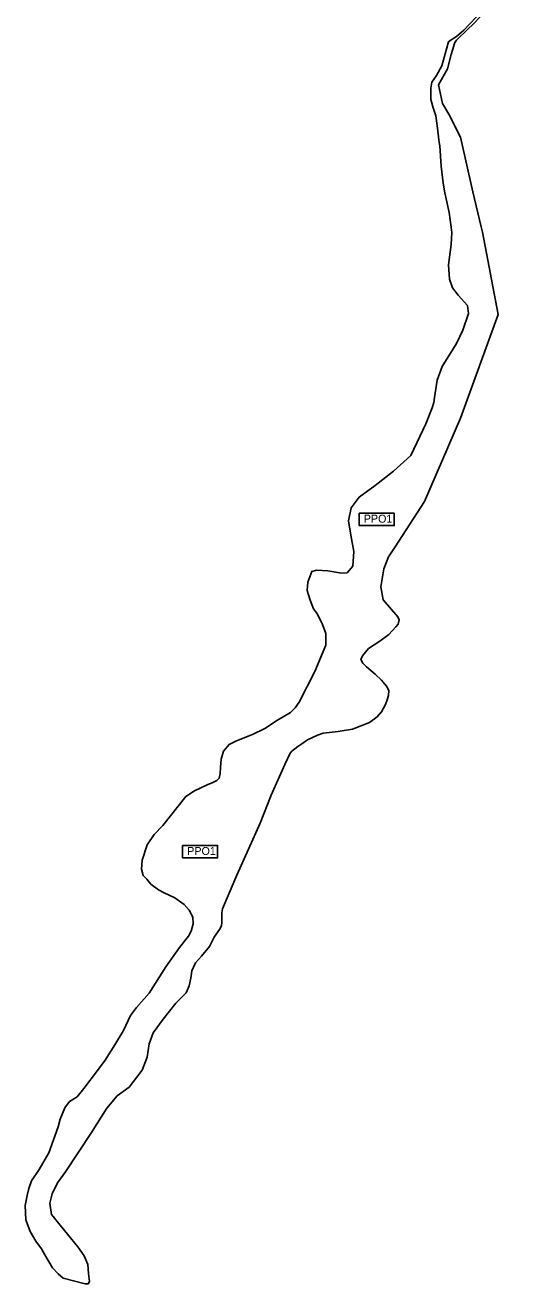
# Model space of a CAD drawing. Extents: x -545342 to -528609, y -1041871 to -1035695.
# Drawn here: x -543416 to -542812, y -1041655 to -1040083 of the extents above; entities that cross this region are included whole.
import ezdxf

# ---------------------------------------------------------------- set-up
doc = ezdxf.new("R2010")
doc.units = 0
doc.layers.add('Vrstva 61', color=7, linetype='Continuous')
doc.layers.add('Vrstva 7', color=7, linetype='Continuous')

msp = doc.modelspace()

# ---------------------------------------------------------------- linework, layer by layer
at = {"layer": 'Vrstva 61'}
for points in [[(-542862.3, -1040087.3), (-542856.8, -1040082), (-542835.7, -1040060.5), (-542826.2, -1040049.6), (-542818.1, -1040039.5), (-542817.2, -1040038.4), (-542811.6, -1040031.3), (-542814.1, -1040031.2), (-542816.3, -1040032.9), (-542827.5, -1040046.1), (-542844.5, -1040064.4), (-542867.8, -1040088.9), (-542877.2, -1040096.9), (-542883.6, -1040101.1)], [(-542877, -1040101.7), (-542862.3, -1040087.3)], [(-542883.6, -1040335.1), (-542882.7, -1040342), (-542883.5, -1040356.9), (-542887, -1040382.4), (-542885.9, -1040400), (-542881.9, -1040410.9), (-542874.9, -1040420.2), (-542863.3, -1040433.2), (-542862.2, -1040443.1), (-542869.3, -1040464.1), (-542877.2, -1040480.4), (-542894.9, -1040509.3), (-542901.3, -1040526.4), (-542904.7, -1040547.9), (-542905.5, -1040554.2), (-542907.3, -1040560.9), (-542915.4, -1040581.1), (-542934.3, -1040620.4), (-542955.7, -1040639.9), (-542978.5, -1040658.1), (-542998.5, -1040672.5), (-543008.7, -1040686), (-543012, -1040701.9), (-543009.2, -1040720), (-543005.4, -1040740.5), (-543006.6, -1040758.6), (-543013.8, -1040767.1), (-543020.7, -1040767.6), (-543038, -1040764.7), (-543051.8, -1040763.9), (-543057.9, -1040765.6), (-543063, -1040778.6), (-543063.9, -1040789.3), (-543059.8, -1040801.4), (-543055.6, -1040812.1), (-543050.8, -1040818.7), (-543044.7, -1040831.5), (-543040.4, -1040842.9), (-543040.4, -1040857.5), (-543054.3, -1040890.5), (-543073.5, -1040928.7), (-543078.5, -1040935.9), (-543084.7, -1040941.7), (-543100.9, -1040951.3), (-543116.8, -1040961.4), (-543132.2, -1040968.9), (-543151.9, -1040976.8), (-543161.4, -1040981.5), (-543168.1, -1040990), (-543171, -1040999.8), (-543171.9, -1041010.4), (-543172.6, -1041017.7), (-543173.8, -1041023.4), (-543176.7, -1041026.7), (-543181.7, -1041029.1), (-543188.9, -1041031.8), (-543204.6, -1041039.5), (-543215.5, -1041046.7), (-543244.1, -1041082.8), (-543255, -1041094), (-543263.5, -1041106.8), (-543270.1, -1041126.2), (-543270.9, -1041137.1), (-543268.8, -1041145.1), (-543264.3, -1041149.9), (-543259, -1041156), (-543249.7, -1041163.3), (-543242.5, -1041166.7), (-543229.2, -1041173.1), (-543217.3, -1041181.6), (-543211.2, -1041188.5), (-543206.6, -1041197.3), (-543206.4, -1041205.5), (-543208.8, -1041214.6), (-543212, -1041221.2), (-543223.4, -1041235), (-543240.4, -1041259.2), (-543261.3, -1041292.3), (-543277.2, -1041310.1), (-543284.4, -1041320.3), (-543293.4, -1041338.9), (-543304.3, -1041356.7), (-543316.3, -1041375.8), (-543325.8, -1041388.8), (-543342.8, -1041411.2), (-543351.3, -1041421.6), (-543360.6, -1041427.4), (-543366.5, -1041435.4), (-543372.3, -1041449.8), (-543375, -1041459.3), (-543386.6, -1041491.6), (-543398.8, -1041512.4), (-543408.1, -1041526.8), (-543411.8, -1041536.3), (-543413.9, -1041544.8), (-543416.2, -1041557.5), (-543415.4, -1041575.6), (-543410.1, -1041589.9), (-543402.9, -1041602), (-543395.7, -1041611.8), (-543391.7, -1041619.2), (-543381.9, -1041635.5), (-543375, -1041642.8), (-543368.5, -1041648.4), (-543341.3, -1041655.3), (-543337.4, -1041655.3), (-543335.8, -1041652.4), (-543337.2, -1041642.6), (-543337.7, -1041631.4), (-543342.3, -1041620.3), (-543350.2, -1041609.1), (-543363.3, -1041593.3), (-543383.2, -1041568.6), (-543385.4, -1041554.5), (-543382.6, -1041542.8), (-543375.7, -1041529.3), (-543365.9, -1041515.4), (-543333.3, -1041466.1), (-543314.2, -1041435.8), (-543301.2, -1041420.5), (-543286.4, -1041409.5), (-543270.1, -1041388.5), (-543263.5, -1041372.3), (-543261.2, -1041355.6), (-543256.1, -1041341.6), (-543243.5, -1041324.9), (-543227.7, -1041304.8), (-543214.9, -1041291.8), (-543211.4, -1041283), (-543209, -1041273.5), (-543207.7, -1041264.4), (-543203.2, -1041254.3), (-543195.8, -1041246.1), (-543185.7, -1041233.8), (-543180.1, -1041222.4), (-543172.6, -1041211.5), (-543170.9, -1041207.5), (-543170.3, -1041204.2), (-543170.3, -1041199.7), (-543170.4, -1041191.9), (-543169.5, -1041186.8), (-543151.6, -1041144.9), (-543122.4, -1041080), (-543108.5, -1041045), (-543091.5, -1041006.7), (-543085.1, -1040992.4), (-543082.8, -1040989.8), (-543079, -1040986.8), (-543075.4, -1040984.2), (-543070.2, -1040980.7), (-543063.1, -1040975.8), (-543050.7, -1040970), (-543043.8, -1040967.3), (-543024.9, -1040965.2), (-543006.9, -1040962.5), (-542985.6, -1040954), (-542976.1, -1040946.9), (-542970.8, -1040940.8), (-542965.9, -1040931.5), (-542963.5, -1040925.8), (-542961.9, -1040920.5), (-542961.7, -1040913.9), (-542964.6, -1040908.6), (-542970.7, -1040901.1), (-542978.9, -1040893.7), (-542989.5, -1040884.6), (-542994.3, -1040880.1), (-542996.7, -1040875.3), (-542994.6, -1040870.8), (-542986.9, -1040861.8), (-542972.7, -1040852.5), (-542961.7, -1040844), (-542952.7, -1040834.4), (-542949.8, -1040831.2), (-542948.7, -1040825.9), (-542950.2, -1040822.1), (-542968.9, -1040800.9), (-542971.7, -1040784.7), (-542967.9, -1040762.1), (-542961.9, -1040747.2), (-542953.5, -1040734.7), (-542916.9, -1040677.8), (-542872.1, -1040574), (-542824.9, -1040444.5), (-542844.7, -1040341.3), (-542846.2, -1040334.8), (-542856.7, -1040291), (-542872.2, -1040222.8), (-542886.6, -1040194), (-542894.5, -1040180.8), (-542899.7, -1040157.5), (-542888.3, -1040137.4), (-542883.9, -1040119.3), (-542880.4, -1040108.6), (-542880.3, -1040108.3)], [(-542886.9, -1040103.5), (-542895.2, -1040133.5), (-542902.2, -1040145.8), (-542908, -1040154.1), (-542909.3, -1040161.7), (-542909, -1040175.7), (-542906.2, -1040186.2), (-542903, -1040196), (-542901, -1040208.1), (-542898.6, -1040229.4), (-542897.7, -1040233.7), (-542896.4, -1040258.9), (-542893.8, -1040280.3), (-542891.5, -1040292.3), (-542886.1, -1040317), (-542883.6, -1040335.1)], [(-542883.6, -1040101.1), (-542886.9, -1040103.5)], [(-542880.3, -1040108.3), (-542879, -1040104.7), (-542877, -1040101.7)]]:
    msp.add_lwpolyline(points, dxfattribs=at)
at = {"layer": 'Vrstva 7'}
for points in [[(-542998.7, -1040692.6), (-542954.9, -1040692.6), (-542954.9, -1040708.1), (-542998.7, -1040708.1)], [(-543219.4, -1041107.7), (-543175.6, -1041107.7), (-543175.6, -1041123.2), (-543219.4, -1041123.2)]]:
    msp.add_lwpolyline(points, close=True, dxfattribs=at)

# ---------------------------------------------------------------- texts
for p in [(-542992.9, -1040704.4), (-543213.6, -1041119.6)]:
    msp.add_text('PPO1', height=10, dxfattribs=at).set_placement(p)

doc.saveas('drawing.dxf')
